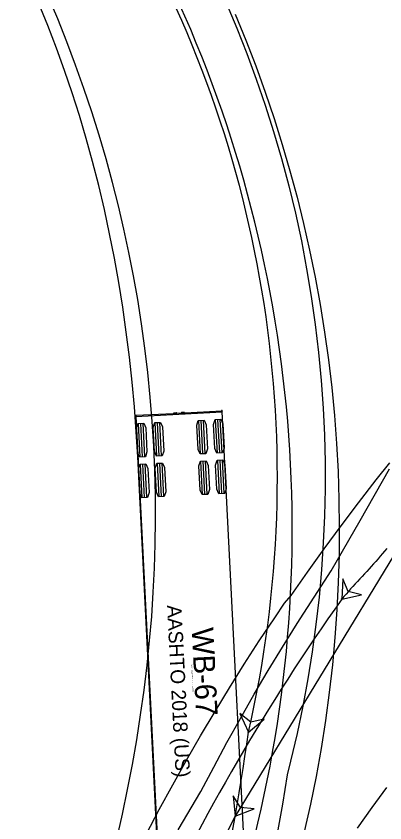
# Model space of a CAD drawing. Extents: x 973688 to 979179, y 703586 to 707602.
# Drawn here: x 973973.5 to 974009.7, y 707313.5 to 707392.7 of the extents above; entities that cross this region are included whole.
import ezdxf

# ---------------------------------------------------------------- set-up
doc = ezdxf.new("R2010")
doc.units = 0
doc.layers.add('0-NPLT', color=7, linetype='Continuous')
doc.layers.add('NO PLOT', color=7, linetype='Continuous')

msp = doc.modelspace()

# ---------------------------------------------------------------- linework, layer by layer
at = {"layer": '0-NPLT'}
msp.add_line((974024.503, 707362.779), (973994.992, 707314.135), dxfattribs=at)
msp.add_line((974024.503, 707362.779), (973994.992, 707314.135), dxfattribs=at)
for points in [[(973983.374, 707311.884), (973983.92, 707314.318), (973984.426, 707316.756), (973984.891, 707319.197), (973985.315, 707321.641), (973985.697, 707324.085), (973986.037, 707326.53), (973986.334, 707328.975), (973986.583, 707331.39), (973986.786, 707333.764), (973986.946, 707336.132), (973987.062, 707338.496), (973987.136, 707340.856), (973987.166, 707343.241), (973987.152, 707345.659), (973987.093, 707348.076), (973986.989, 707350.491), (973986.839, 707352.903), (973986.645, 707355.311), (973986.405, 707357.714), (973986.12, 707360.111), (973985.79, 707362.502), (973985.415, 707364.888), (973985.005, 707367.205), (973984.554, 707369.511), (973984.059, 707371.808), (973983.523, 707374.095), (973982.943, 707376.374), (973982.306, 707378.7), (973981.624, 707381.018), (973980.899, 707383.327), (973980.13, 707385.624), (973979.319, 707387.911), (973978.466, 707390.186), (973977.571, 707392.449), (973976.635, 707394.699)], [(973983.374, 707311.884), (973983.92, 707314.318), (973984.426, 707316.756), (973984.891, 707319.197), (973985.315, 707321.641), (973985.697, 707324.085), (973986.037, 707326.53), (973986.334, 707328.975), (973986.583, 707331.39), (973986.786, 707333.764), (973986.946, 707336.132), (973987.062, 707338.496), (973987.136, 707340.856), (973987.166, 707343.241), (973987.152, 707345.659), (973987.093, 707348.076), (973986.989, 707350.491), (973986.839, 707352.903), (973986.645, 707355.311), (973986.405, 707357.714), (973986.12, 707360.111), (973985.79, 707362.502), (973985.415, 707364.888), (973985.005, 707367.205), (973984.554, 707369.511), (973984.059, 707371.808), (973983.523, 707374.095), (973982.943, 707376.374), (973982.306, 707378.7), (973981.624, 707381.018), (973980.899, 707383.327), (973980.13, 707385.624), (973979.319, 707387.911), (973978.466, 707390.186), (973977.571, 707392.449), (973976.635, 707394.699)], [(973994.989, 707392.902), (973996.021, 707390.377), (973997, 707387.83), (973997.927, 707385.261), (973998.8, 707382.672), (973999.607, 707380.1), (974000.356, 707377.531), (974001.053, 707374.946), (974001.697, 707372.345), (974002.287, 707369.728), (974002.824, 707367.099), (974003.318, 707364.397), (974003.754, 707361.684), (974004.134, 707358.961), (974004.456, 707356.229), (974004.72, 707353.49), (974004.927, 707350.745), (974005.075, 707347.996), (974005.166, 707345.243), (974005.198, 707342.489), (974005.173, 707339.803), (974005.093, 707337.105), (974004.956, 707334.405), (974004.764, 707331.704), (974004.514, 707329.003), (974004.205, 707326.274), (974003.833, 707323.52), (974003.402, 707320.774), (974002.913, 707318.038), (974002.366, 707315.314), (974001.761, 707312.603)], [(973994.989, 707392.902), (973996.021, 707390.377), (973997, 707387.83), (973997.927, 707385.261), (973998.8, 707382.672), (973999.607, 707380.1), (974000.356, 707377.531), (974001.053, 707374.946), (974001.697, 707372.345), (974002.287, 707369.728), (974002.824, 707367.099), (974003.318, 707364.397), (974003.754, 707361.684), (974004.134, 707358.961), (974004.456, 707356.229), (974004.72, 707353.49), (974004.927, 707350.745), (974005.075, 707347.996), (974005.166, 707345.243), (974005.198, 707342.489), (974005.173, 707339.803), (974005.093, 707337.105), (974004.956, 707334.405), (974004.764, 707331.704), (974004.514, 707329.003), (974004.205, 707326.274), (974003.833, 707323.52), (974003.402, 707320.774), (974002.913, 707318.038), (974002.366, 707315.314), (974001.761, 707312.603)], [(973989.392, 707312.801), (973991.62, 707316.554), (973992.872, 707318.959), (973994.162, 707321.358), (973995.489, 707323.747), (973996.853, 707326.126), (973998.219, 707328.437), (973999.627, 707330.746), (974001.072, 707333.047), (974004.395, 707338.227), (974007.242, 707343.178), (974010.119, 707348.244)], [(973989.392, 707312.801), (973991.62, 707316.554), (973992.872, 707318.959), (973994.162, 707321.358), (973995.489, 707323.747), (973996.853, 707326.126), (973998.219, 707328.437), (973999.627, 707330.746), (974001.072, 707333.047), (974004.395, 707338.227), (974007.242, 707343.178), (974010.119, 707348.244)], [(973994.992, 707314.135), (973996.856, 707314.86), (973995.511, 707314.99), (973994.774, 707316.123), (973994.992, 707314.135)], [(973994.992, 707314.135), (973996.856, 707314.86), (973995.511, 707314.99), (973994.774, 707316.123), (973994.992, 707314.135)]]:
    msp.add_lwpolyline(points, dxfattribs=at)
msp.add_lwpolyline([(973994.992, 707314.135), (973996.856, 707314.86), (973995.511, 707314.99), (973994.774, 707316.123)], close=True, dxfattribs=at)
msp.add_lwpolyline([(973994.992, 707314.135), (973996.856, 707314.86), (973995.511, 707314.99), (973994.774, 707316.123)], close=True, dxfattribs=at)
msp.add_circle((973994.992, 707314.135), 0.0417, dxfattribs=at)
msp.add_circle((973994.992, 707314.135), 0.0417, dxfattribs=at)
msp.add_circle((973994.992, 707314.135), 0.0417, dxfattribs=at)
msp.add_circle((973994.992, 707314.135), 0.0417, dxfattribs=at)
for centre, radius, start, end in [((973874.844, 707342.338), 125.735, 344.09743, 25.58118), ((973874.844, 707342.338), 125.735, 344.09743, 25.58118), ((974170.093, 707224.287), 196.807, 152.83657, 166.91405), ((974170.093, 707224.287), 196.807, 152.83657, 166.91405)]:
    msp.add_arc(centre, radius, start, end, dxfattribs=at)
at = {"layer": 'NO PLOT'}
for p, q in [((973985.227, 707353.409), (973993.716, 707353.84)), ((973988.937, 707353.668), (973989.203, 707353.682)), ((973989.468, 707353.695), (973989.472, 707353.625)), ((973989.733, 707353.708), (973989.999, 707353.722)), ((973985.659, 707349.417), (973985.492, 707352.713)), ((973985.888, 707349.429), (973985.721, 707352.724)), ((973986.117, 707349.44), (973985.95, 707352.736)), ((973987.307, 707349.501), (973987.14, 707352.796)), ((973987.536, 707349.512), (973987.369, 707352.808)), ((973987.765, 707349.524), (973987.597, 707352.82)), ((973991.585, 707349.718), (973991.418, 707353.014)), ((973991.814, 707349.729), (973991.646, 707353.025)), ((973992.043, 707349.741), (973991.875, 707353.037)), ((973993.233, 707349.801), (973993.065, 707353.097)), ((973993.462, 707349.813), (973993.294, 707353.109)), ((973993.69, 707349.825), (973993.523, 707353.12)), ((973985.862, 707345.422), (973985.695, 707348.718)), ((973986.091, 707345.434), (973985.923, 707348.73)), ((973986.32, 707345.445), (973986.152, 707348.741)), ((973987.51, 707345.506), (973987.342, 707348.802)), ((973987.739, 707345.517), (973987.571, 707348.813)), ((973987.968, 707345.529), (973987.8, 707348.825)), ((973991.788, 707345.723), (973991.62, 707349.019)), ((973992.016, 707345.735), (973991.849, 707349.03)), ((973992.245, 707345.746), (973992.078, 707349.042)), ((973993.436, 707345.807), (973993.268, 707349.102)), ((973993.664, 707345.818), (973993.497, 707349.114)), ((973993.893, 707345.83), (973993.726, 707349.126)), ((974005.434, 707335.454), (974005.434, 707335.454))]:
    msp.add_line(p, q, dxfattribs=at)
for points in [[(973987.788, 707302.618), (973985.429, 707349.422), (973985.28, 707351.902), (973985.095, 707354.342), (973984.87, 707356.782), (973984.603, 707359.238), (973984.296, 707361.684), (973983.948, 707364.121), (973983.559, 707366.545), (973983.128, 707368.957), (973982.655, 707371.354), (973982.141, 707373.736), (973981.584, 707376.101), (973980.984, 707378.445), (973980.359, 707380.712), (973979.692, 707382.956), (973978.985, 707385.18), (973978.235, 707387.384), (973977.443, 707389.573), (973976.586, 707391.805), (973975.684, 707394.021)], [(973994.09, 707394.019), (973995.132, 707391.554), (973996.12, 707389.059), (973997.052, 707386.534), (973997.928, 707383.982), (973998.751, 707381.391), (973999.527, 707378.732), (974000.239, 707376.053), (974000.889, 707373.356), (974001.474, 707370.643), (974001.994, 707367.916), (974002.45, 707365.177), (974002.84, 707362.427), (974003.164, 707359.668), (974003.421, 707356.925), (974003.61, 707354.225), (974003.735, 707351.549), (974003.799, 707348.896), (974003.802, 707346.265), (974003.746, 707343.655), (974003.629, 707340.99), (974003.45, 707338.321), (974003.21, 707335.649), (974002.906, 707332.974), (974002.54, 707330.296), (974002.109, 707327.614), (974001.613, 707324.93), (974001.05, 707322.242), (974000.421, 707319.55), (974000.081, 707318.203), (973999.613, 707315.306), (973999.112, 707312.44)], [(973985.246, 707353.481), (973985.224, 707353.48), (973985.228, 707353.409), (973985.514, 707347.749), (973987.907, 707300.618), (973992.151, 707300.834), (973996.396, 707301.049), (973994.003, 707348.18), (973993.715, 707353.84), (973993.712, 707353.91), (973993.69, 707353.909)], [(973989.202, 707353.752), (973988.935, 707353.739), (973988.934, 707353.738), (973988.937, 707353.668), (973988.902, 707353.666), (973985.271, 707353.482), (973985.27, 707353.482)], [(973989.726, 707353.708), (973989.206, 707353.682)], [(973993.666, 707353.908), (973993.665, 707353.908), (973990.034, 707353.724), (973989.999, 707353.722), (973989.995, 707353.792), (973989.994, 707353.792), (973989.727, 707353.779)], [(973986.251, 707312.342), (973987.534, 707314.781), (973988.85, 707317.209), (973990.201, 707319.626), (973991.585, 707322.032), (973993.001, 707324.42), (973994.416, 707326.741), (973995.866, 707329.053), (973997.347, 707331.35), (973998.859, 707333.632), (973999.824, 707335.047), (974000.489, 707335.826), (974002.082, 707338.106), (974003.716, 707340.396), (974005.385, 707342.67), (974007.089, 707344.927), (974008.829, 707347.168), (974010.157, 707348.839)], [(974009.86, 707340.437), (974009.647, 707340.18), (974009.433, 707339.925), (974009.218, 707339.671), (974009.001, 707339.418), (974008.782, 707339.166), (974008.561, 707338.916), (974008.339, 707338.668), (974008.115, 707338.421), (974007.889, 707338.176), (974007.662, 707337.932), (974007.433, 707337.69), (974007.205, 707337.446), (974006.979, 707337.202), (974006.754, 707336.956), (974006.53, 707336.709), (974006.308, 707336.46), (974006.087, 707336.211), (974005.868, 707335.96), (974005.65, 707335.707), (974005.434, 707335.454)], [(974005.434, 707335.454), (974007.389, 707335.873), (974006.082, 707336.215), (974005.535, 707337.451), (974005.434, 707335.454)], [(973996.283, 707322.4), (973997.824, 707323.673), (973996.506, 707323.374), (973995.451, 707324.219), (973996.283, 707322.4)], [(974009.832, 707316.966), (974008.389, 707314.993), (974006.943, 707312.954)]]:
    msp.add_lwpolyline(points, dxfattribs=at)
for points in [[(973986.174, 707349.443), (973985.602, 707349.414), (973985.407, 707349.867), (973985.286, 707352.24), (973985.435, 707352.71), (973986.006, 707352.739), (973986.202, 707352.286), (973986.322, 707349.913)], [(973987.822, 707349.527), (973987.25, 707349.498), (973987.055, 707349.95), (973986.934, 707352.323), (973987.083, 707352.794), (973987.654, 707352.823), (973987.85, 707352.37), (973987.97, 707349.997)], [(973992.099, 707349.744), (973991.528, 707349.715), (973991.333, 707350.168), (973991.212, 707352.541), (973991.361, 707353.011), (973991.932, 707353.04), (973992.128, 707352.587), (973992.248, 707350.214)], [(973993.747, 707349.828), (973993.176, 707349.799), (973992.98, 707350.251), (973992.86, 707352.624), (973993.009, 707353.094), (973993.58, 707353.123), (973993.775, 707352.671), (973993.896, 707350.298)], [(973986.376, 707345.448), (973985.805, 707345.419), (973985.61, 707345.872), (973985.489, 707348.245), (973985.638, 707348.715), (973986.209, 707348.744), (973986.405, 707348.291), (973986.525, 707345.918)], [(973988.024, 707345.532), (973987.453, 707345.503), (973987.258, 707345.956), (973987.137, 707348.329), (973987.286, 707348.799), (973987.857, 707348.828), (973988.053, 707348.375), (973988.173, 707346.002)], [(973992.302, 707345.749), (973991.731, 707345.72), (973991.535, 707346.173), (973991.415, 707348.546), (973991.564, 707349.016), (973992.135, 707349.045), (973992.33, 707348.592), (973992.451, 707346.219)], [(973993.95, 707345.833), (973993.379, 707345.804), (973993.183, 707346.256), (973993.063, 707348.629), (973993.211, 707349.099), (973993.783, 707349.128), (973993.978, 707348.676), (973994.099, 707346.303)], [(974005.434, 707335.454), (974007.389, 707335.873), (974006.082, 707336.215), (974005.535, 707337.451)], [(973996.283, 707322.4), (973997.824, 707323.673), (973996.506, 707323.374), (973995.451, 707324.219)]]:
    msp.add_lwpolyline(points, close=True, dxfattribs=at)
for centre, radius in [((973985.256, 707353.515), 0.0266), ((973993.677, 707353.943), 0.0266), ((974005.434, 707335.454), 0.0417), ((974005.434, 707335.454), 0.0417), ((974005.434, 707335.454), 0.0417), ((974005.434, 707335.454), 0.0417), ((973996.283, 707322.4), 0.0417), ((973996.283, 707322.4), 0.0417)]:
    msp.add_circle(centre, radius, dxfattribs=at)
for centre, radius, start, end in [((973887.29, 707347.441), 111.832, 347.06067, 30.48185), ((973985.143, 707355.5), 2.022, 272.90606, 273.58982), ((973989.203, 707353.717), 0.0354, 97.1976, 269.38306), ((973989.204, 707353.717), 0.0352, 273.88038, 92.88079), ((973989.729, 707353.744), 0.0352, 92.93133, 271.93174), ((973989.729, 707353.744), 0.0353, 276.24224, 94.59189), ((973993.677, 707353.943), 0.0363, 291.98351, 253.14486), ((974179.595, 707212.24), 213.339, 144.72191, 165.04007), ((973777.621, 707352.668), 220.746, 342.09837, 352.11889)]:
    msp.add_arc(centre, radius, start, end, dxfattribs=at)

# ---------------------------------------------------------------- texts
for s, height, p in [('AASHTO 2018 (US)', 1.41667, (973988.29, 707334.847)), ('WB-67', 2.125, (973990.708, 707332.614)), ('(c) 2021 Transoft Solutions, Inc. All rights reserved.', 0.085, (973990.678, 707329.028))]:
    msp.add_text(s, height=height, rotation=272.90606, dxfattribs=at).set_placement(p)

doc.saveas('drawing.dxf')
